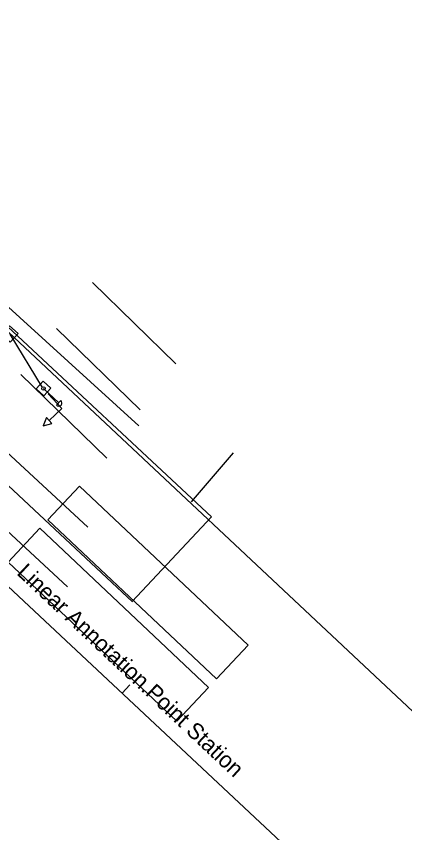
# Model space of a CAD drawing. Extents: x 1470334 to 1482043, y 378207 to 388330.
# Drawn here: x 1480220.4 to 1480287.5, y 379336.3 to 379477.2 of the extents above; entities that cross this region are included whole.
import ezdxf

# ---------------------------------------------------------------- set-up
doc = ezdxf.new("R2010")
doc.units = 0
for name, color, linetype in [('Default', 7, 'Continuous'), ('GK_Drainage_Nodes', 7, 'Continuous'), ('GK_Visualization', 7, 'Continuous'), ('PM_X_Cells', 7, 'Continuous'), ('PM_X_Surveyed_Line', 7, 'Continuous'), ('PV_X_Driveway', 7, 'Continuous'), ('PV_X_Parking_Lot', 7, 'Continuous'), ('SV_X_Break_Lines', 7, 'Continuous'), ('SV_X_Text_Elevation', 7, 'Continuous'), ('UT_X_Gas_Cells', 7, 'Continuous'), ('VG_X_Cells', 7, 'Continuous')]:
    doc.layers.add(name, color=color, linetype=linetype)

msp = doc.modelspace()

# ---------------------------------------------------------------- linework, layer by layer
at = {"layer": 'Default'}
for p, q in [((1479566.69, 379989.53), (1480555.97, 379063.33)), ((1480250.68, 379393.41), (1480257.91, 379401.81)), ((1480238.7, 379360.37), (1480240.06, 379361.83))]:
    msp.add_line(p, q, dxfattribs=at)
at = {"layer": 'GK_Drainage_Nodes'}
for p, q in [((1480248, 379417.19), (1480233.57, 379431.21)), ((1480241.81, 379409.26), (1480227.39, 379423.28)), ((1480236.07, 379400.89), (1480221.2, 379415.35))]:
    msp.add_line(p, q, dxfattribs=at)
at = {"layer": 'GK_Visualization'}
msp.add_lwpolyline([(1480225.19, 379411.66), (1480226.41, 379412.98), (1480225.08, 379414.2), (1480223.86, 379412.87)], close=True, dxfattribs=at)
msp.add_circle((1480225.13, 379412.93), 0.3, dxfattribs=at)
at = {"layer": 'PM_X_Cells'}
msp.add_line((1480225.13, 379412.93), (1480225.13, 379412.93), dxfattribs=at)
msp.add_lwpolyline([(1480225.95, 379412.04), (1480228.32, 379409.47), (1480226.11, 379407.44)], dxfattribs=at)
msp.add_lwpolyline([(1480226.58, 379406.92), (1480225.64, 379407.95), (1480225.08, 379406.49)], close=True, dxfattribs=at)
at = {"layer": 'PM_X_Surveyed_Line'}
msp.add_line((1480005.18, 379622.84), (1480577.77, 379086.76), dxfattribs=at)
at = {"layer": 'PV_X_Driveway'}
msp.add_line((1480219.33, 379422.34), (1480224.91, 379413.13), dxfattribs=at)
at = {"layer": 'PV_X_Parking_Lot'}
msp.add_lwpolyline([(1480219.26, 379423.76), (1480220.75, 379422.42), (1480219.41, 379420.93), (1480217.92, 379422.27)], close=True, dxfattribs=at)
at = {"layer": 'SV_X_Break_Lines'}
msp.add_line((1480216.59, 379429.25), (1480241.59, 379406.51), dxfattribs=at)
at = {"layer": 'SV_X_Text_Elevation'}
for p, q in [((1480232.78, 379389.02), (1480170.4, 379446.76)), ((1480229.26, 379378.73), (1480158.19, 379444.5))]:
    msp.add_line(p, q, dxfattribs=at)
at = {"layer": 'UT_X_Gas_Cells'}
for p, q in [((1480225.13, 379412.93), (1480227.76, 379410.47)), ((1480228.15, 379410.88), (1480227.38, 379410.06))]:
    msp.add_line(p, q, dxfattribs=at)
for points in [[(1480254.98, 379362.83), (1480260.47, 379368.65), (1480231.36, 379396.09), (1480225.88, 379390.27)], [(1480248.12, 379355.55), (1480253.61, 379361.37), (1480224.5, 379388.81), (1480219.02, 379382.99)]]:
    msp.add_lwpolyline(points, close=True, dxfattribs=at)
msp.add_arc((1480227.76, 379410.47), 0.56, 226.9499, 46.9495, dxfattribs=at)
at = {"layer": 'VG_X_Cells'}
for p, q in [((1480162.34, 379476.3), (1480254.13, 379390.77)), ((1480240.5, 379376.14), (1480161.44, 379449.8)), ((1480254.13, 379390.77), (1480240.46, 379376.17))]:
    msp.add_line(p, q, dxfattribs=at)

# ---------------------------------------------------------------- texts
at = {"layer": 'Default'}
msp.add_text('Linear Annotation.Point Station', height=2.8, rotation=316.886, dxfattribs=at).set_placement((1480220.37, 379380.96))

doc.saveas('drawing.dxf')
